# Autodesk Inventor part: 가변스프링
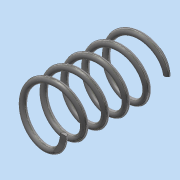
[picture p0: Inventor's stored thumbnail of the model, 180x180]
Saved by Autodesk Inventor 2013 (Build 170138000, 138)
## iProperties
Created: 2017-02
Part Number: 가변스프링
Material: 강철, 탄소
Document SubType Name: Modeling
Designer: dgall
Density: 7.87 g/cm^3
Mass: 6.52222 g
Surface Area: 16.802 cm^2
Volume: 0.828744 cm^3
Author: dgall
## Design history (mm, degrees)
sketch "스케치1"
  geometry: L1 (0, 0)-(8.5, 0); L2 (19.466, 35)-(0, 35); L3 (0, 35)-(0, 0); C1 r 1 at (8.5, 0)
  constraints: 6 end point, 1 centre point, 1 coincident, 1 horizontal, 1 parallel, 1 vertical
  dimensions: "d0" = 2 diameter of C1; "d2" = 35 distance of L2.end L1.start (derived); "d3" = 17 diameter of L1.end L3
feature "코일1" sketch "스케치1" pitch "d4" = 10; turns "d6" = 5; dims "d5" = 35 (= d2), "d7" = 0, angle "d8" = 90 deg, angle "d9" = 90 deg, "d10" = 0, "d11" = 0
node "작업 평면1"
node "작업 평면2"
feature "분할1"
feature "분할2"
node "솔리드1"
other parameters: "d12" = 0, "d13" = 0
